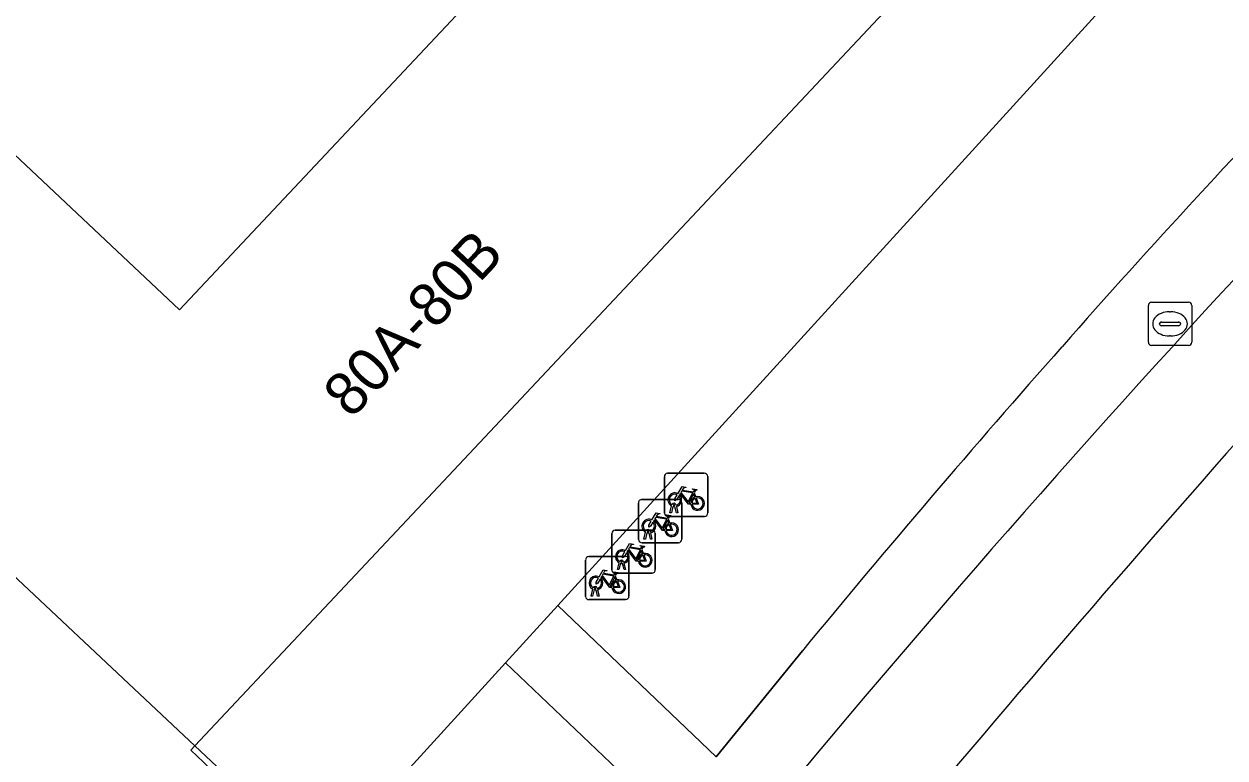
# Model space of a CAD drawing. Extents: x 159039 to 160102, y 381214 to 382524.
# Drawn here: x 159467.3 to 159495.04, y 381538.57 to 381555.53 of the extents above; entities that cross this region are included whole.
import ezdxf

# ---------------------------------------------------------------- set-up
doc = ezdxf.new("R2010")
doc.units = 0
for name, color, linetype in [('IMGEO_Berm_groen', 7, 'Continuous'), ('IMGEO_Erf', 7, 'Continuous'), ('IMGEO_Fietsenrek', 7, 'Continuous'), ('IMGEO_Fietspad_gesloten', 7, 'Continuous'), ('IMGEO_Groenvoorziening', 7, 'Continuous'), ('IMGEO_Kolk', 7, 'Continuous'), ('IMGEO_Pand', 7, 'Continuous'), ('IMGEO_Pand_nummerreeks', 7, 'Continuous'), ('IMGEO_Voetpad_open', 7, 'Continuous')]:
    doc.layers.add(name, color=color, linetype=linetype)

msp = doc.modelspace()

# ---------------------------------------------------------------- linework, layer by layer
at = {"layer": 'IMGEO_Berm_groen'}
msp.add_arc((159807.274, 381269.803), 416.575, 137.82976, 141.62035, dxfattribs=at)
at = {"layer": 'IMGEO_Erf'}
for points in [[(159464.308, 381586.475), (159470.174, 381580.964), (159476.042, 381575.453), (159481.909, 381569.943), (159487.883, 381564.332), (159483.395, 381559.555), (159487.27, 381555.916), (159471.246, 381538.856), (159474.176, 381536.104), (159478.425, 381540.77), (159479.629, 381542.092), (159494.82, 381558.774), (159492.689, 381560.816), (159451.02, 381600.164)], [(159466.281, 381553.264), (159470.896, 381548.93), (159477.649, 381556.12), (159477.948, 381555.839), (159479.992, 381558.015), (159475.037, 381562.627), (159473.247, 381560.704), (159470.848, 381562.937), (159472.638, 381564.86), (159469.146, 381568.111), (159463.254, 381573.596)]]:
    msp.add_lwpolyline(points, dxfattribs=at)
at = {"layer": 'IMGEO_Fietsenrek'}
for p, q in [((159482.094, 381544.228), (159482.094, 381545.069)), ((159482.094, 381545.069), (159482.094, 381544.228)), ((159482.169, 381545.153), (159483.01, 381545.153)), ((159483.01, 381545.153), (159482.169, 381545.153)), ((159483.094, 381545.078), (159483.094, 381544.237)), ((159483.094, 381544.237), (159483.094, 381545.078)), ((159481.569, 381544.546), (159482.41, 381544.546)), ((159482.41, 381544.546), (159481.569, 381544.546)), ((159482.781, 381544.702), (159482.817, 381544.607)), ((159481.494, 381543.621), (159481.494, 381544.462)), ((159481.494, 381544.462), (159481.494, 381543.621)), ((159482.221, 381544.237), (159482.26, 381544.397)), ((159482.255, 381544.237), (159482.221, 381544.237)), ((159482.29, 381544.385), (159482.255, 381544.237)), ((159482.332, 381544.409), (159482.331, 381544.413)), ((159482.373, 381544.237), (159482.339, 381544.379)), ((159482.363, 381544.42), (159482.364, 381544.413)), ((159482.371, 381544.383), (159482.406, 381544.237)), ((159482.406, 381544.237), (159482.373, 381544.237)), ((159482.494, 381544.471), (159482.494, 381543.63)), ((159482.494, 381543.63), (159482.494, 381544.471)), ((159483.019, 381544.153), (159482.178, 381544.153)), ((159482.178, 381544.153), (159483.019, 381544.153)), ((159482.181, 381544.095), (159482.217, 381544)), ((159480.883, 381542.915), (159480.883, 381543.756)), ((159480.883, 381543.756), (159480.883, 381542.915)), ((159480.958, 381543.84), (159481.799, 381543.84)), ((159481.799, 381543.84), (159480.958, 381543.84)), ((159481.621, 381543.63), (159481.66, 381543.79)), ((159481.69, 381543.778), (159481.655, 381543.63)), ((159481.732, 381543.802), (159481.731, 381543.806)), ((159481.773, 381543.63), (159481.739, 381543.772)), ((159481.763, 381543.813), (159481.764, 381543.806)), ((159481.771, 381543.776), (159481.806, 381543.63)), ((159481.883, 381543.765), (159481.883, 381542.924)), ((159481.883, 381542.924), (159481.883, 381543.765)), ((159482.419, 381543.546), (159481.578, 381543.546)), ((159481.578, 381543.546), (159482.419, 381543.546)), ((159481.655, 381543.63), (159481.621, 381543.63)), ((159481.806, 381543.63), (159481.773, 381543.63)), ((159480.273, 381542.306), (159480.273, 381543.147)), ((159480.273, 381543.147), (159480.273, 381542.306)), ((159480.348, 381543.231), (159481.189, 381543.231)), ((159481.189, 381543.231), (159480.348, 381543.231)), ((159481.273, 381543.156), (159481.273, 381542.315)), ((159481.273, 381542.315), (159481.273, 381543.156)), ((159481.57, 381543.389), (159481.606, 381543.294)), ((159481.01, 381542.924), (159481.049, 381543.084)), ((159481.044, 381542.924), (159481.01, 381542.924)), ((159481.079, 381543.072), (159481.044, 381542.924)), ((159481.121, 381543.096), (159481.12, 381543.1)), ((159481.162, 381542.924), (159481.128, 381543.066)), ((159481.152, 381543.107), (159481.153, 381543.1)), ((159481.16, 381543.07), (159481.195, 381542.924)), ((159481.195, 381542.924), (159481.162, 381542.924)), ((159480.96, 381542.78), (159480.996, 381542.685)), ((159481.808, 381542.84), (159480.967, 381542.84)), ((159480.967, 381542.84), (159481.808, 381542.84)), ((159480.4, 381542.315), (159480.439, 381542.475)), ((159480.434, 381542.315), (159480.4, 381542.315)), ((159480.469, 381542.463), (159480.434, 381542.315)), ((159480.511, 381542.487), (159480.51, 381542.491)), ((159480.552, 381542.315), (159480.518, 381542.457)), ((159480.542, 381542.498), (159480.543, 381542.491)), ((159480.55, 381542.461), (159480.585, 381542.315)), ((159480.585, 381542.315), (159480.552, 381542.315)), ((159481.198, 381542.231), (159480.357, 381542.231)), ((159480.357, 381542.231), (159481.198, 381542.231))]:
    msp.add_line(p, q, dxfattribs=at)
for points in [[(159482.407, 381544.679), (159482.502, 381544.843), (159482.588, 381544.829), (159482.59, 381544.82), (159482.534, 381544.809), (159482.507, 381544.764), (159482.763, 381544.723)], [(159482.763, 381544.723), (159482.788, 381544.772), (159482.782, 381544.776), (159482.759, 381544.78), (159482.747, 381544.787), (159482.746, 381544.79), (159482.748, 381544.795), (159482.843, 381544.78), (159482.845, 381544.77), (159482.835, 381544.757), (159482.823, 381544.751), (159482.809, 381544.757), (159482.781, 381544.702)], [(159482.428, 381544.627), (159482.376, 381544.537), (159482.336, 381544.512), (159482.337, 381544.559), (159482.392, 381544.653)], [(159482.703, 381544.435), (159482.653, 381544.435), (159482.462, 381544.686), (159482.443, 381544.654)], [(159482.75, 381544.698), (159482.493, 381544.739), (159482.476, 381544.71), (159482.643, 381544.49), (159482.75, 381544.698)], [(159482.798, 381544.6), (159482.768, 381544.677), (159482.659, 381544.459), (159482.702, 381544.459)], [(159482.732, 381544.459), (159482.852, 381544.458), (159482.808, 381544.572)], [(159482.828, 381544.579), (159482.883, 381544.434), (159482.733, 381544.434)], [(159481.807, 381544.072), (159481.902, 381544.236), (159481.988, 381544.222), (159481.99, 381544.213), (159481.934, 381544.202), (159481.907, 381544.157), (159482.163, 381544.116)], [(159481.828, 381544.02), (159481.776, 381543.93), (159481.736, 381543.905), (159481.737, 381543.952), (159481.792, 381544.046)], [(159482.103, 381543.828), (159482.053, 381543.828), (159481.862, 381544.079), (159481.843, 381544.047)], [(159482.15, 381544.091), (159481.893, 381544.132), (159481.876, 381544.103), (159482.043, 381543.883), (159482.15, 381544.091)], [(159482.198, 381543.993), (159482.168, 381544.07), (159482.059, 381543.852), (159482.102, 381543.852)], [(159482.132, 381543.852), (159482.252, 381543.851), (159482.208, 381543.965)], [(159482.228, 381543.972), (159482.283, 381543.827), (159482.133, 381543.827)], [(159482.163, 381544.116), (159482.188, 381544.165), (159482.182, 381544.169), (159482.159, 381544.173), (159482.147, 381544.18), (159482.146, 381544.183), (159482.148, 381544.188), (159482.243, 381544.173), (159482.245, 381544.163), (159482.235, 381544.15), (159482.223, 381544.144), (159482.209, 381544.15), (159482.181, 381544.095)], [(159481.196, 381543.366), (159481.291, 381543.53), (159481.377, 381543.516), (159481.379, 381543.507), (159481.323, 381543.496), (159481.296, 381543.451), (159481.552, 381543.41)], [(159481.539, 381543.385), (159481.282, 381543.426), (159481.265, 381543.397), (159481.432, 381543.177), (159481.539, 381543.385)], [(159481.552, 381543.41), (159481.577, 381543.459), (159481.571, 381543.463), (159481.548, 381543.467), (159481.536, 381543.474), (159481.535, 381543.477), (159481.537, 381543.482), (159481.632, 381543.467), (159481.634, 381543.457), (159481.624, 381543.444), (159481.612, 381543.438), (159481.598, 381543.444), (159481.57, 381543.389)], [(159481.217, 381543.314), (159481.165, 381543.224), (159481.125, 381543.199), (159481.126, 381543.246), (159481.181, 381543.34)], [(159481.492, 381543.122), (159481.442, 381543.122), (159481.251, 381543.373), (159481.232, 381543.341)], [(159481.587, 381543.287), (159481.557, 381543.364), (159481.448, 381543.146), (159481.491, 381543.146)], [(159481.521, 381543.146), (159481.641, 381543.145), (159481.597, 381543.259)], [(159481.617, 381543.266), (159481.672, 381543.121), (159481.522, 381543.121)], [(159480.586, 381542.757), (159480.681, 381542.921), (159480.767, 381542.907), (159480.769, 381542.898), (159480.713, 381542.887), (159480.686, 381542.842), (159480.942, 381542.801)], [(159480.942, 381542.801), (159480.967, 381542.85), (159480.961, 381542.854), (159480.938, 381542.858), (159480.926, 381542.865), (159480.925, 381542.868), (159480.927, 381542.873), (159481.022, 381542.858), (159481.024, 381542.848), (159481.014, 381542.835), (159481.002, 381542.829), (159480.988, 381542.835), (159480.96, 381542.78)], [(159480.607, 381542.705), (159480.555, 381542.615), (159480.515, 381542.59), (159480.516, 381542.637), (159480.571, 381542.731)], [(159480.882, 381542.513), (159480.832, 381542.513), (159480.641, 381542.764), (159480.622, 381542.732)], [(159480.929, 381542.776), (159480.672, 381542.817), (159480.655, 381542.788), (159480.822, 381542.568), (159480.929, 381542.776)], [(159480.977, 381542.678), (159480.947, 381542.755), (159480.838, 381542.537), (159480.881, 381542.537)], [(159480.911, 381542.537), (159481.031, 381542.536), (159480.987, 381542.65)], [(159481.007, 381542.657), (159481.062, 381542.512), (159480.912, 381542.512)]]:
    msp.add_lwpolyline(points, dxfattribs=at)
for centre, radius, start, end in [((159482.172, 381545.075), 0.0779, 92.4484, 184.2845), ((159482.172, 381545.075), 0.0779, 92.4484, 184.2845), ((159483.016, 381545.075), 0.0779, 2.4484, 94.2845), ((159483.016, 381545.075), 0.0779, 2.4484, 94.2845), ((159481.572, 381544.468), 0.0779, 92.4484, 184.2845), ((159481.572, 381544.468), 0.0779, 92.4484, 184.2845), ((159482.334, 381544.538), 0.159, 62.6766, 242.1369), ((159482.334, 381544.538), 0.129, 63.3192, 238.903), ((159482.334, 381544.538), 0.129, 283.6043, 43.4302), ((159482.334, 381544.538), 0.159, 283.5766, 46.6042), ((159482.416, 381544.468), 0.0779, 2.4484, 94.2845), ((159482.416, 381544.468), 0.0779, 2.4484, 94.2845), ((159482.861, 381544.454), 0.159, 113.3408, 178.3217), ((159482.861, 381544.454), 0.159, 187.0065, 105.7708), ((159482.861, 381544.454), 0.129, 113.923, 177.9556), ((159482.861, 381544.454), 0.129, 188.6715, 104.5883), ((159482.314, 381544.409), 0.0499, 12.8025, 158.6934), ((159482.334, 381544.538), 0.159, 253.9967, 271.7867), ((159482.314, 381544.409), 0.0174, 12.8025, 163.4502), ((159482.334, 381544.538), 0.129, 253.415, 269.0204), ((159483.016, 381544.231), 0.0779, 272.4484, 4.2845), ((159483.016, 381544.231), 0.0779, 272.4484, 4.2845), ((159481.734, 381543.931), 0.159, 62.6766, 242.1369), ((159481.734, 381543.931), 0.129, 63.3192, 238.903), ((159481.734, 381543.931), 0.129, 283.6043, 43.4302), ((159481.734, 381543.931), 0.159, 283.5766, 46.6042), ((159482.172, 381544.231), 0.0779, 182.4484, 274.2845), ((159482.172, 381544.231), 0.0779, 182.4484, 274.2845), ((159482.261, 381543.847), 0.159, 113.3408, 178.3217), ((159482.261, 381543.847), 0.159, 187.0065, 105.7708), ((159482.261, 381543.847), 0.129, 113.923, 177.9556), ((159482.261, 381543.847), 0.129, 188.6715, 104.5883), ((159480.961, 381543.762), 0.0779, 92.4484, 184.2845), ((159480.961, 381543.762), 0.0779, 92.4484, 184.2845), ((159481.714, 381543.802), 0.0499, 12.8025, 158.6934), ((159481.734, 381543.931), 0.159, 253.9967, 271.7867), ((159481.714, 381543.802), 0.0174, 12.8025, 163.4502), ((159481.734, 381543.931), 0.129, 253.415, 269.0204), ((159481.805, 381543.762), 0.0779, 2.4484, 94.2845), ((159481.805, 381543.762), 0.0779, 2.4484, 94.2845), ((159481.572, 381543.624), 0.0779, 182.4484, 274.2845), ((159481.572, 381543.624), 0.0779, 182.4484, 274.2845), ((159482.416, 381543.624), 0.0779, 272.4484, 4.2845), ((159482.416, 381543.624), 0.0779, 272.4484, 4.2845), ((159480.351, 381543.153), 0.0779, 92.4484, 184.2845), ((159480.351, 381543.153), 0.0779, 92.4484, 184.2845), ((159481.123, 381543.225), 0.159, 62.6766, 242.1369), ((159481.123, 381543.225), 0.129, 63.3192, 238.903), ((159481.103, 381543.096), 0.0499, 12.8025, 158.6934), ((159481.123, 381543.225), 0.129, 283.6043, 43.4302), ((159481.123, 381543.225), 0.159, 283.5766, 46.6042), ((159481.195, 381543.153), 0.0779, 2.4484, 94.2845), ((159481.195, 381543.153), 0.0779, 2.4484, 94.2845), ((159481.65, 381543.141), 0.159, 113.3408, 178.3217), ((159481.65, 381543.141), 0.159, 187.0065, 105.7708), ((159481.65, 381543.141), 0.129, 113.923, 177.9556), ((159481.65, 381543.141), 0.129, 188.6715, 104.5883), ((159480.961, 381542.918), 0.0779, 182.4484, 274.2845), ((159480.961, 381542.918), 0.0779, 182.4484, 274.2845), ((159481.123, 381543.225), 0.159, 253.9967, 271.7867), ((159481.103, 381543.096), 0.0174, 12.8025, 163.4502), ((159481.123, 381543.225), 0.129, 253.415, 269.0204), ((159481.805, 381542.918), 0.0779, 272.4484, 4.2845), ((159481.805, 381542.918), 0.0779, 272.4484, 4.2845), ((159480.513, 381542.616), 0.159, 62.6766, 242.1369), ((159480.513, 381542.616), 0.129, 63.3192, 238.903), ((159480.513, 381542.616), 0.129, 283.6043, 43.4302), ((159480.513, 381542.616), 0.159, 283.5766, 46.6042), ((159481.04, 381542.532), 0.159, 113.3408, 178.3217), ((159481.04, 381542.532), 0.159, 187.0065, 105.7708), ((159481.04, 381542.532), 0.129, 113.923, 177.9556), ((159481.04, 381542.532), 0.129, 188.6715, 104.5883), ((159480.351, 381542.309), 0.0779, 182.4484, 274.2845), ((159480.351, 381542.309), 0.0779, 182.4484, 274.2845), ((159480.493, 381542.487), 0.0499, 12.8025, 158.6934), ((159480.513, 381542.616), 0.159, 253.9967, 271.7867), ((159480.493, 381542.487), 0.0174, 12.8025, 163.4502), ((159480.513, 381542.616), 0.129, 253.415, 269.0204), ((159481.195, 381542.309), 0.0779, 272.4484, 4.2845), ((159481.195, 381542.309), 0.0779, 272.4484, 4.2845)]:
    msp.add_arc(centre, radius, start, end, dxfattribs=at)
at = {"layer": 'IMGEO_Fietspad_gesloten'}
for centre, radius, start, end in [((159714.564, 381347.031), 298.57, 135.70827, 142.7), ((159807.274, 381269.803), 416.575, 137.82976, 141.62035)]:
    msp.add_arc(centre, radius, start, end, dxfattribs=at)
at = {"layer": 'IMGEO_Groenvoorziening'}
msp.add_lwpolyline([(159497.62, 381554.946), (159498.193, 381555.541), (159494.82, 381558.774), (159479.629, 381542.092), (159483.291, 381538.599), (159485.281, 381541.046)], dxfattribs=at)
msp.add_lwpolyline([(159482.14, 381537.23), (159478.425, 381540.77), (159474.176, 381536.104), (159471.246, 381538.856), (159471.156, 381538.756), (159471.444, 381538.475), (159473.798, 381536.22), (159478.068, 381532.212)], close=True, dxfattribs=at)
for centre, radius, start, end in [((159642.548, 381414.797), 201.608, 135.96039, 138.61737), ((159685.418, 381376.387), 259.167, 138.51157, 140.55482)]:
    msp.add_arc(centre, radius, start, end, dxfattribs=at)
at = {"layer": 'IMGEO_Kolk'}
for p, q in [((159493.274, 381548.178), (159493.274, 381549.03)), ((159493.349, 381549.104), (159494.201, 381549.104)), ((159494.275, 381549.03), (159494.275, 381548.178)), ((159493.762, 381548.884), (159493.787, 381548.884)), ((159493.533, 381548.598), (159493.533, 381548.61)), ((159493.971, 381548.561), (159493.573, 381548.561)), ((159493.576, 381548.647), (159493.974, 381548.647)), ((159494.017, 381548.61), (159494.017, 381548.598)), ((159493.785, 381548.324), (159493.76, 381548.324)), ((159494.201, 381548.104), (159493.349, 381548.104))]:
    msp.add_line(p, q, dxfattribs=at)
for points in [[(159493.274, 381548.178), (159493.274, 381549.03)], [(159493.349, 381549.104), (159494.201, 381549.104)], [(159494.275, 381549.03), (159494.275, 381548.178)], [(159494.201, 381548.104), (159493.349, 381548.104)]]:
    msp.add_lwpolyline(points, dxfattribs=at)
for centre, radius, start, end in [((159493.351, 381549.028), 0.0765, 91.552, 178.448), ((159493.351, 381549.028), 0.0765, 91.552, 178.448), ((159494.199, 381549.028), 0.0765, 1.552, 88.448), ((159494.199, 381549.028), 0.0765, 1.552, 88.448), ((159493.573, 381548.607), 0.0403, 85.8775, 175.7526), ((159493.57, 381548.597), 0.0366, 178.938, 274.7102), ((159493.974, 381548.604), 0.043, 264.8664, 352.4533), ((159493.978, 381548.609), 0.0386, 1.7309, 96.639), ((159493.351, 381548.18), 0.0765, 181.552, 268.448), ((159493.351, 381548.18), 0.0765, 181.552, 268.448), ((159494.199, 381548.18), 0.0765, 271.552, 358.448), ((159494.199, 381548.18), 0.0765, 271.552, 358.448)]:
    msp.add_arc(centre, radius, start, end, dxfattribs=at)
for centre, major_axis, ratio, start_param, end_param in [((159493.761, 381548.604), (-0.387, 0.002), 0.722429, 4.712389, 7.853982), ((159493.786, 381548.604), (-0.39, 0.002), 0.717154, 1.570796, 4.712389)]:
    msp.add_ellipse(centre, major_axis=major_axis, ratio=ratio, start_param=start_param, end_param=end_param, dxfattribs=at)
at = {"layer": 'IMGEO_Pand'}
msp.add_lwpolyline([(159481.909, 381569.943), (159475.037, 381562.627), (159479.992, 381558.015), (159477.948, 381555.839), (159477.649, 381556.12), (159470.896, 381548.93), (159466.281, 381553.264), (159461.398, 381548.106), (159471.246, 381538.856), (159487.27, 381555.916), (159483.395, 381559.555), (159487.883, 381564.332)], close=True, dxfattribs=at)
at = {"layer": 'IMGEO_Voetpad_open'}
for points in [[(159466.875, 381538.044), (159468.846, 381536.185), (159469.96, 381537.34), (159476.972, 381530.775), (159478.068, 381532.212), (159473.798, 381536.22), (159471.444, 381538.475), (159471.156, 381538.756), (159471.246, 381538.856), (159461.398, 381548.106)], [(159485.281, 381541.046), (159483.291, 381538.599), (159479.629, 381542.092), (159478.425, 381540.77), (159482.14, 381537.23), (159478.068, 381532.212), (159476.972, 381530.775), (159475.948, 381529.546), (159475.828, 381529.637), (159475.156, 381528.804)]]:
    msp.add_lwpolyline(points, dxfattribs=at)
for centre, radius, start, end in [((159714.564, 381347.031), 298.57, 135.70827, 142.7), ((159642.548, 381414.797), 201.608, 135.96039, 138.61737), ((159685.418, 381376.387), 259.167, 138.51157, 140.55482)]:
    msp.add_arc(centre, radius, start, end, dxfattribs=at)

# ---------------------------------------------------------------- texts
at = {"layer": 'IMGEO_Pand_nummerreeks'}
msp.add_text('80A-80B', height=1, rotation=46.7936, dxfattribs=at).set_placement((159474.863, 381546.389))

doc.saveas('drawing.dxf')
